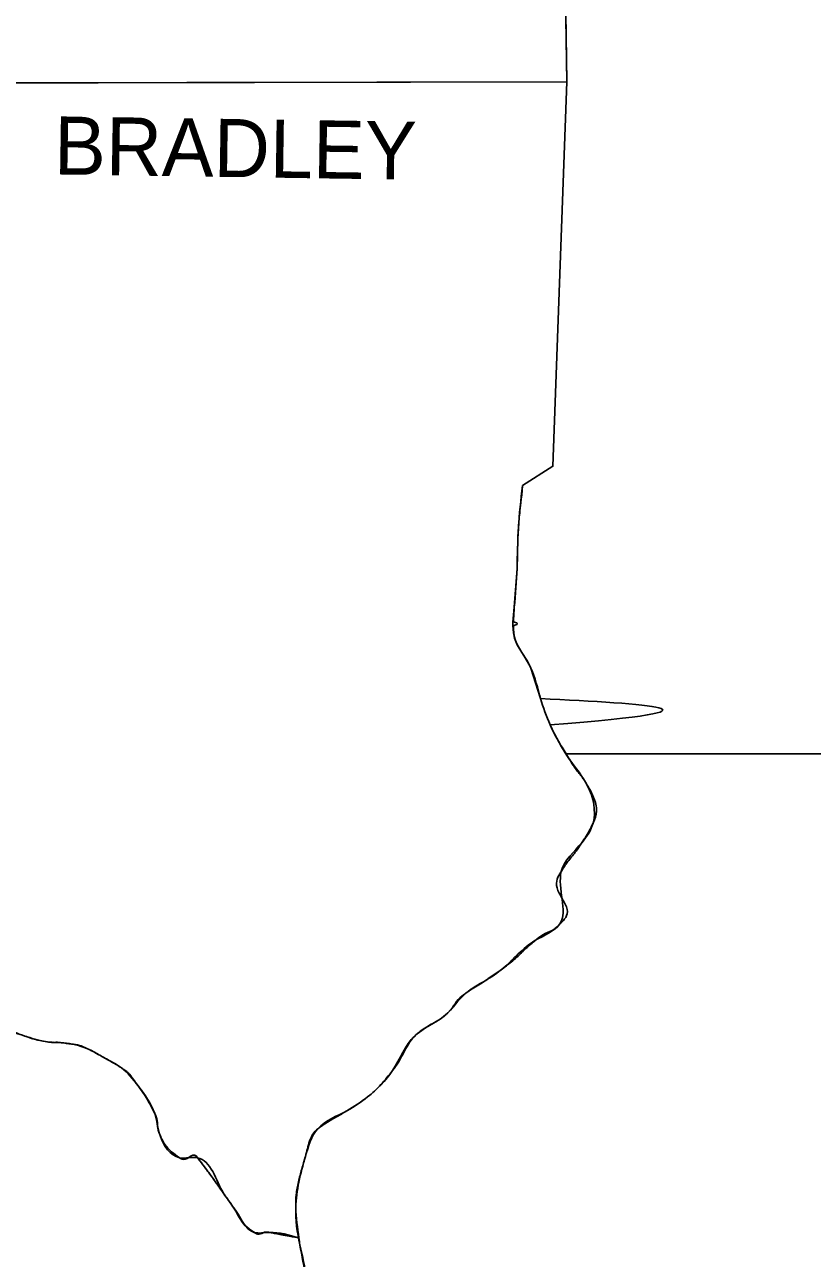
# Model space of a CAD drawing. Extents: x 3046 to 131673, y -8885 to 10756.
# Drawn here: x 104619 to 105176, y 5284 to 6157 of the extents above; entities that cross this region are included whole.
import ezdxf

# ---------------------------------------------------------------- set-up
doc = ezdxf.new("R2010")
doc.units = 0
for name, color, linetype in [('1', 7, 'Continuous'), ('2', 7, 'Continuous'), ('R_Annotation', 7, 'Continuous')]:
    doc.layers.add(name, color=color, linetype=linetype)

msp = doc.modelspace()

# ---------------------------------------------------------------- linework, layer by layer
at = {"layer": '1'}
for points in [[(105016.39229155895, 6645.919519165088), (105017.37069846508, 6523.618667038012), (104996.82415519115, 6522.640260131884), (105002.69459609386, 6116.601431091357)], [(105016.39229155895, 6645.919519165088), (105017.37069846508, 6523.618667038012), (104996.82415519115, 6522.640260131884), (105002.69459609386, 6116.601431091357)], [(104560.45471461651, 6115.623024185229), (105002.69459609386, 6116.601431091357)], [(104560.45471461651, 6115.623024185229), (105002.69459609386, 6116.601431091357)], [(105002.69459609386, 6116.601431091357), (104992.91052790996, 5844.604335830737), (104971.38557792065, 5830.906640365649)], [(105002.69459609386, 6116.601431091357), (104992.91052790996, 5844.604335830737), (104971.38557792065, 5830.906640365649)], [(105002.29871516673, 5641.095717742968), (105644.52946822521, 5641.095717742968)], [(105002.29871516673, 5641.095717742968), (105644.52946822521, 5641.095717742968)]]:
    msp.add_lwpolyline(points, dxfattribs=at)
for points in [[(104971.38557792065, 5830.906640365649), (104968.45035750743, 5800.576028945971), (104967.4719506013, 5772.202231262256), (104965.5151369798, 5744.806840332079), (104965.5151369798, 5724.260297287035), (104977.25601882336, 5701.75694050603), (104984.1048666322, 5680.2319904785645), (104990.95371428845, 5661.642260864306), (105004.65140975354, 5637.182090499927), (105017.37069846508, 5618.592361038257), (105021.28432555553, 5592.175376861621), (105013.45707118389, 5578.477681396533), (104998.78096881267, 5557.931138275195), (104997.80256209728, 5520.7516791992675), (104980.19123935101, 5509.0107973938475), (104957.68788245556, 5489.4426611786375), (104944.9685938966, 5480.636999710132), (104931.27089843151, 5471.831338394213), (104916.59479625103, 5456.176829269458), (104895.06984626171, 5441.500726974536), (104879.41533713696, 5417.040556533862), (104861.80401439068, 5398.450827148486), (104847.1279122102, 5388.66675892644), (104826.58136893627, 5375.947470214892), (104817.77570762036, 5356.379333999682), (104810.92686000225, 5320.178281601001), (104813.86208033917, 5293.7612975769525), (104817.77570762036, 5270.279533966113), (104812.88367347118, 5240.927329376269), (104817.77570762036, 5208.639904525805), (104822.66774165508, 5183.201327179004), (104830.49499617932, 5160.697970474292), (104841.25747126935, 5135.2593932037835), (104854.95516673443, 5111.77762951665), (104884.30737113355, 5075.57657734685)], [(104971.38557792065, 5830.906640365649), (104968.45035750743, 5800.576028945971), (104967.4719506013, 5772.202231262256), (104965.5151369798, 5744.806840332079), (104965.5151369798, 5724.260297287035), (104977.25601882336, 5701.75694050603), (104984.1048666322, 5680.2319904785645), (104990.95371428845, 5661.642260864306), (105004.65140975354, 5637.182090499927), (105017.37069846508, 5618.592361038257), (105021.28432555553, 5592.175376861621), (105013.45707118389, 5578.477681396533), (104998.78096881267, 5557.931138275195), (104997.80256209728, 5520.7516791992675), (104980.19123935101, 5509.0107973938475), (104957.68788245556, 5489.4426611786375), (104944.9685938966, 5480.636999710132), (104931.27089843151, 5471.831338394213), (104916.59479625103, 5456.176829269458), (104895.06984626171, 5441.500726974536), (104879.41533713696, 5417.040556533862), (104861.80401439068, 5398.450827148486), (104847.1279122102, 5388.66675892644), (104826.58136893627, 5375.947470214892), (104817.77570762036, 5356.379333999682), (104810.92686000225, 5320.178281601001), (104813.86208033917, 5293.7612975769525), (104817.77570762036, 5270.279533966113), (104812.88367347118, 5240.927329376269), (104817.77570762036, 5208.639904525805), (104822.66774165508, 5183.201327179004), (104830.49499617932, 5160.697970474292), (104841.25747126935, 5135.2593932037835), (104854.95516673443, 5111.77762951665), (104884.30737113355, 5075.57657734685)], [(103995.91398108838, 5604.894665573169), (104011.56849017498, 5615.657140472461), (104026.24459235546, 5621.5275813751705), (104040.92069472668, 5618.592361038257), (104056.5752036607, 5616.635547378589), (104070.27289912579, 5618.592361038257), (104087.88422187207, 5615.657140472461), (104102.56032420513, 5606.851479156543), (104119.19324004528, 5600.0026314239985), (104135.82615588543, 5600.0026314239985), (104150.50225825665, 5600.0026314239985), (104163.2215468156, 5591.196970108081), (104186.70331042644, 5592.175376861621), (104206.2714468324, 5600.0026314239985), (104225.83958316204, 5605.873072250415), (104252.25656722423, 5608.80829281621), (104275.73833087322, 5592.175376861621), (104292.37124671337, 5578.477681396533), (104306.06894214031, 5562.823172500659), (104315.85301032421, 5545.2118497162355), (104326.6154852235, 5535.427781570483), (104344.22680796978, 5528.578933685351), (104357.92450343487, 5525.643713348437), (104374.55741946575, 5520.7516791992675), (104383.36308070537, 5516.838051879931), (104391.19033526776, 5498.2483224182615), (104403.90962378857, 5472.809745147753), (104428.36979438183, 5464.004083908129), (104458.70040564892, 5475.744965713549), (104483.16057605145, 5482.593813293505), (104500.77189875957, 5488.46425427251), (104511.53437388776, 5492.377881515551), (104521.31844207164, 5493.356288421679), (104518.38322150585, 5495.313102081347), (104530.12410331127, 5498.2483224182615), (104540.88657824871, 5490.421067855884), (104547.73542605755, 5479.658592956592), (104559.47630790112, 5464.004083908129), (104570.23878280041, 5450.306388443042), (104581.00125792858, 5445.414354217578), (104591.76373282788, 5451.2847951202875), (104606.43983500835, 5446.392761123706), (104619.15912375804, 5441.500726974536), (104633.83522593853, 5437.587099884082), (104646.55451465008, 5436.608692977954), (104663.18743045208, 5432.695065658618), (104675.90671904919, 5425.846218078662), (104687.64760089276, 5418.99737019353), (104699.38848269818, 5406.27808163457), (104711.12936450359, 5386.7099453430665), (104715.04299178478, 5371.05543621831), (104728.74068724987, 5355.400927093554), (104741.45997596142, 5355.400927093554), (104760.0497054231, 5329.962349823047), (104766.89855307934, 5320.178281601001), (104781.57465545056, 5302.56695889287), (104792.33713034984, 5302.56695889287), (104812.88367347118, 5298.653331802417)], [(103995.91398108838, 5604.894665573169), (104011.56849017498, 5615.657140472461), (104026.24459235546, 5621.5275813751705), (104040.92069472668, 5618.592361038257), (104056.5752036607, 5616.635547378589), (104070.27289912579, 5618.592361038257), (104087.88422187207, 5615.657140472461), (104102.56032420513, 5606.851479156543), (104119.19324004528, 5600.0026314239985), (104135.82615588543, 5600.0026314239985), (104150.50225825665, 5600.0026314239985), (104163.2215468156, 5591.196970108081), (104186.70331042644, 5592.175376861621), (104206.2714468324, 5600.0026314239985), (104225.83958316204, 5605.873072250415), (104252.25656722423, 5608.80829281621), (104275.73833087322, 5592.175376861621), (104292.37124671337, 5578.477681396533), (104306.06894214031, 5562.823172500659), (104315.85301032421, 5545.2118497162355), (104326.6154852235, 5535.427781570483), (104344.22680796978, 5528.578933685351), (104357.92450343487, 5525.643713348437), (104374.55741946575, 5520.7516791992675), (104383.36308070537, 5516.838051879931), (104391.19033526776, 5498.2483224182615), (104403.90962378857, 5472.809745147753), (104428.36979438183, 5464.004083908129), (104458.70040564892, 5475.744965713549), (104483.16057605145, 5482.593813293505), (104500.77189875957, 5488.46425427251), (104511.53437388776, 5492.377881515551), (104521.31844207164, 5493.356288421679), (104518.38322150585, 5495.313102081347), (104530.12410331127, 5498.2483224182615), (104540.88657824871, 5490.421067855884), (104547.73542605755, 5479.658592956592), (104559.47630790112, 5464.004083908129), (104570.23878280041, 5450.306388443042), (104581.00125792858, 5445.414354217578), (104591.76373282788, 5451.2847951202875), (104606.43983500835, 5446.392761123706), (104619.15912375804, 5441.500726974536), (104633.83522593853, 5437.587099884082), (104646.55451465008, 5436.608692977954), (104663.18743045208, 5432.695065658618), (104675.90671904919, 5425.846218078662), (104687.64760089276, 5418.99737019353), (104699.38848269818, 5406.27808163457), (104711.12936450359, 5386.7099453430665), (104715.04299178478, 5371.05543621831), (104728.74068724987, 5355.400927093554), (104741.45997596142, 5355.400927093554), (104760.0497054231, 5329.962349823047), (104766.89855307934, 5320.178281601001), (104781.57465545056, 5302.56695889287), (104792.33713034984, 5302.56695889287), (104812.88367347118, 5298.653331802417)]]:
    msp.add_spline(points, degree=3, dxfattribs=at)
at = {"layer": 'R_Annotation'}
for p, q in [((105002.69459609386, 6116.601431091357), (105000.77090721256, 6249.656578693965)), ((104560.45471461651, 6115.623024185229), (105002.69459609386, 6116.601431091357)), ((105002.69459609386, 6116.601431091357), (104560.45471461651, 6115.623024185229)), ((104965.51513698, 5744.80684033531), (104967.4719506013, 5772.202231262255)), ((104965.03865341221, 5729.387249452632), (104964.96825096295, 5731.752196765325)), ((104965.5151369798, 5724.260297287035), (104965.0386534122, 5729.387249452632)), ((104965.7927240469, 5722.806812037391), (104965.5151369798, 5724.260297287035)), ((104970.83445782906, 5712.848559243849), (104967.48304469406, 5718.314513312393)), ((104974.46143100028, 5707.462635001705), (104970.83445782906, 5712.848559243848)), ((104975.18640380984, 5706.248617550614), (104974.46143100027, 5707.462635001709)), ((104977.25601882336, 5701.756940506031), (104975.18640380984, 5706.248617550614)), ((104984.1048666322, 5680.2319904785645), (104977.25601882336, 5701.75694050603)), ((104790.5125638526, 5302.64464065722), (104784.94675413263, 5301.746018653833)), ((104812.88367347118, 5298.653331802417), (104792.33713034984, 5302.56695889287)), ((104813.18348168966, 5298.6941528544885), (104812.88367347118, 5298.653331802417))]:
    msp.add_line(p, q, dxfattribs=at)
for points in [[(104971.38557792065, 5830.906640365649), (104992.91052790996, 5844.604335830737), (105002.69459609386, 6116.601431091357)], [(104812.88367347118, 5298.653331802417), (104813.18348168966, 5298.6941528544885)]]:
    msp.add_lwpolyline(points, dxfattribs=at)
for points, degree in [([(104967.4719506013, 5772.202231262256), (104967.95987127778, 5781.648834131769), (104967.83472158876, 5791.13343925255), (104968.45035750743, 5800.576028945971), (104969.11113276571, 5810.710963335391), (104970.54819890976, 5820.7888765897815), (104971.38557792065, 5830.906640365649)], 3), ([(104912.48513079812, 5453.0516838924), (104913.93521610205, 5454.004300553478), (104915.3211835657, 5455.027802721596), (104916.59479625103, 5456.176829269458), (104921.84691487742, 5460.91518010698), (104925.38659641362, 5467.7660836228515), (104931.27089843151, 5471.831338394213), (104935.73631831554, 5474.916338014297), (104940.47477150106, 5477.5960490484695), (104944.9685938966, 5480.636999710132), (104949.23778921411, 5483.5259461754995), (104953.51673986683, 5486.409234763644), (104957.68788245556, 5489.4426611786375), (104965.72856449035, 5495.290175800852), (104972.63054311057, 5502.6530135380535), (104980.19123935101, 5509.0107973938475), (104985.55756298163, 5513.523334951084), (104992.6283219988, 5515.729579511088), (104997.80256209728, 5520.7516791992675), (105006.89452330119, 5529.5763055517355), (104992.23229908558, 5547.591370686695), (104998.78096881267, 5557.931138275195), (105003.22683389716, 5564.950764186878), (105008.89691763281, 5571.35088383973), (105013.45707118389, 5578.477681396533), (105016.30631112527, 5582.930592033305), (105019.24677228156, 5587.450719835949), (105021.28432555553, 5592.175376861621), (105024.73338308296, 5600.173015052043), (105022.00340120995, 5610.836164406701), (105017.37069846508, 5618.592361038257), (105013.46324124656, 5625.134331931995), (105008.46543902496, 5630.732693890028), (105004.65140975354, 5637.182090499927), (104999.90442687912, 5645.2090806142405), (104994.66287095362, 5653.018854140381), (104990.95371428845, 5661.642260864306)], 3), ([(104526.4489948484, 5498.2895980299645), (104527.77603358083, 5498.507009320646), (104529.04028800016, 5498.528174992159), (104530.12410331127, 5498.2483224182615), (104533.80544429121, 5497.297761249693), (104538.16599850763, 5494.106893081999), (104540.88657824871, 5490.421067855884), (104543.49453302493, 5486.8878262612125), (104545.20056692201, 5483.06986031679), (104547.73542605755, 5479.658592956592), (104551.6237224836, 5474.42594767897), (104555.54204939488, 5469.212891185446), (104559.47630790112, 5464.004083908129), (104562.9786819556, 5459.367075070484), (104566.0493375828, 5454.839634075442), (104570.23878280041, 5450.306388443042), (104573.0819560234, 5447.229894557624), (104577.51679466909, 5445.922729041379), (104581.00125792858, 5445.414354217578), (104584.61460166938, 5444.887176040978), (104587.97977203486, 5452.428555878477), (104591.76373282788, 5451.2847951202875), (104596.5386605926, 5449.84149924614), (104601.60180216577, 5448.218975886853), (104606.43983500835, 5446.392761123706), (104610.701699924, 5444.7840327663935), (104614.8697159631, 5443.043456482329), (104619.15912375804, 5441.500726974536), (104623.9399722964, 5439.781245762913), (104628.8524025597, 5438.52568258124), (104633.83522593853, 5437.587099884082), (104638.02018717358, 5436.798805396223), (104642.33978095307, 5437.210001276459), (104646.55451465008, 5436.608692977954), (104652.19992601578, 5435.803272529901), (104657.95340549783, 5435.167223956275), (104663.18743045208, 5432.695065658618), (104667.61243901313, 5430.605025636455), (104671.69378688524, 5428.202973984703), (104675.90671904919, 5425.846218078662), (104679.87073031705, 5423.628710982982), (104683.8117075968, 5421.484634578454), (104687.64760089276, 5418.99737019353), (104692.53254981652, 5415.8298786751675), (104695.85806095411, 5410.993653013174), (104699.38848269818, 5406.27808163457), (104704.04277731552, 5400.061357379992), (104707.8001666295, 5393.541636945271), (104711.12936450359, 5386.7099453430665), (104713.48346290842, 5381.879209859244), (104712.74655418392, 5376.121245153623), (104715.04299178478, 5371.05543621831), (104718.0033169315, 5364.525129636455), (104722.98228923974, 5359.511445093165), (104728.74068724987, 5355.400927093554), (104732.26176662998, 5352.887474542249), (104738.87807919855, 5358.771049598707), (104741.45997596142, 5355.400927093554), (104747.855629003, 5347.0527489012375), (104754.00265373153, 5338.558842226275), (104760.0497054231, 5329.962349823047), (104762.3418786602, 5326.703794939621), (104764.60392083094, 5323.436555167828), (104766.89855307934, 5320.178281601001), (104771.30314960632, 5313.923954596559), (104774.508537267, 5307.179834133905), (104781.57465545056, 5302.56695889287), (104784.8919757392, 5300.401359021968), (104788.81273044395, 5303.231109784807), (104792.33713034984, 5302.56695889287), (104799.18649988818, 5301.276238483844), (104806.03177152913, 5299.9272085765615), (104812.88367347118, 5298.653331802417)], 3), ([(104646.55451465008, 5436.608692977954), (104642.33978095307, 5437.210001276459), (104638.02018717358, 5436.798805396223), (104633.83522593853, 5437.587099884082), (104628.8524025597, 5438.52568258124), (104623.9399722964, 5439.781245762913), (104619.15912375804, 5441.500726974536)], 3), ([(104699.38848269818, 5406.27808163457), (104695.85806095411, 5410.993653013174), (104692.53254981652, 5415.8298786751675), (104687.64760089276, 5418.99737019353), (104683.8117075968, 5421.484634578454), (104679.87073031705, 5423.628710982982), (104675.90671904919, 5425.846218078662), (104671.69378688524, 5428.202973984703), (104667.61243901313, 5430.605025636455), (104663.18743045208, 5432.695065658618), (104657.95340549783, 5435.167223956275), (104652.19992601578, 5435.803272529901), (104646.55451465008, 5436.608692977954)], 3), ([(104700.24883337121, 5405.111554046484), (104699.96546169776, 5405.501576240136), (104699.67871602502, 5405.890418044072), (104699.38848269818, 5406.27808163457)], 2), ([(104741.93220187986, 5354.783682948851), (104741.77494265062, 5354.989519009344), (104741.61753475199, 5355.195267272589), (104741.45997596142, 5355.400927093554), (104738.87807919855, 5358.771049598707), (104732.26176662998, 5352.887474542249), (104728.74068724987, 5355.400927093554), (104722.98228923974, 5359.511445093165), (104718.0033169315, 5364.525129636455), (104715.04299178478, 5371.05543621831), (104712.74655418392, 5376.121245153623), (104713.48346290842, 5381.879209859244), (104711.12936450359, 5386.7099453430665), (104708.0077693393, 5393.115625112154), (104704.5097201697, 5399.2470285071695), (104700.24883337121, 5405.111554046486)], 3), ([(104760.0497054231, 5329.962349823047), (104754.15162462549, 5338.347065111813), (104748.15843584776, 5346.634186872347), (104741.93220187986, 5354.783682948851)], 2), ([(104765.4251194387, 5322.277068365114), (104763.63164340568, 5324.838485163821), (104761.84996752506, 5327.403096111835), (104760.0497054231, 5329.962349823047)], 2), ([(104784.94675413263, 5301.746018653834), (104783.78218541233, 5301.688892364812), (104782.64689857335, 5301.8669813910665), (104781.57465545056, 5302.56695889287), (104774.508537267, 5307.179834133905), (104771.30314960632, 5313.923954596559), (104766.89855307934, 5320.178281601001), (104766.40611422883, 5320.8775224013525), (104765.91517632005, 5321.577176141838), (104765.4251194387, 5322.277068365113)], 3), ([(104792.33713034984, 5302.56695889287), (104791.73873621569, 5302.679722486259), (104791.12891623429, 5302.691766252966), (104790.5125638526, 5302.64464065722)], 2)]:
    msp.add_open_spline(points, degree=degree, dxfattribs=at)
for points in [[(104964.97859240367, 5734.529238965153), (104965.5151369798, 5744.806840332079), (104965.51513698, 5744.806840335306)], [(104964.96825096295, 5731.752196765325), (104964.97859240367, 5734.529238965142), (104964.97859240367, 5734.529238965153)], [(104967.48304469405, 5718.314513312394), (104967.48304469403, 5718.3145133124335), (104965.79272404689, 5722.806812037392)], [(104990.95371428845, 5661.642260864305), (104990.95371428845, 5661.642260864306), (104984.1048666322, 5680.2319904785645)], [(104813.18348168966, 5298.6941528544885), (104810.92686000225, 5320.178281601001), (104811.24533196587, 5329.285020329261), (104812.83501032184, 5338.335191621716), (104815.18282542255, 5347.357171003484), (104817.77570762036, 5356.379333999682), (104820.72740872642, 5367.085566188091), (104823.01725158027, 5371.954798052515), (104826.58136893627, 5375.947470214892), (104829.07786228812, 5377.786217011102), (104836.79633980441, 5382.581306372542), (104842.00048563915, 5385.5452928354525), (104847.1279122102, 5388.66675892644), (104861.80401439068, 5398.450827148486), (104871.18035488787, 5407.1632999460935), (104875.3458945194, 5412.068501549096), (104879.41533713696, 5417.040556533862), (104883.53334643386, 5423.01760673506), (104887.06912721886, 5429.425908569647), (104890.69164024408, 5435.75657699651), (104895.06984626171, 5441.500726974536), (104903.38599017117, 5447.740635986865), (104912.4851307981, 5453.0516838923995)], [(104880.7243214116, 5079.381277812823), (104867.2210683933, 5095.073051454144), (104854.95516673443, 5111.77762951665), (104847.64140736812, 5123.2710694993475), (104841.25747126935, 5135.2593932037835), (104830.49499617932, 5160.697970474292), (104822.66774165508, 5183.201327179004), (104817.77570762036, 5208.639904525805), (104812.88367347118, 5240.927329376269), (104813.32281981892, 5248.265380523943), (104815.32874892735, 5255.603431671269), (104817.33514884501, 5262.941482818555), (104817.84905287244, 5266.610508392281), (104817.77570762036, 5270.279533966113), (104813.86208033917, 5293.7612975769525), (104813.18348168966, 5298.6941528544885)]]:
    msp.add_spline(points, degree=3, dxfattribs=at)

# ---------------------------------------------------------------- texts
at = {"layer": '2'}
msp.add_text('BRADLEY', height=41.081345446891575, rotation=359.144902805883, dxfattribs=at).set_placement((104639.70566684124, 6051.048174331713))
msp.add_text('BRADLEY', height=41.081345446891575, rotation=359.144902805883, dxfattribs=at).set_placement((104639.70566684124, 6051.048174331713))

doc.saveas('drawing.dxf')
